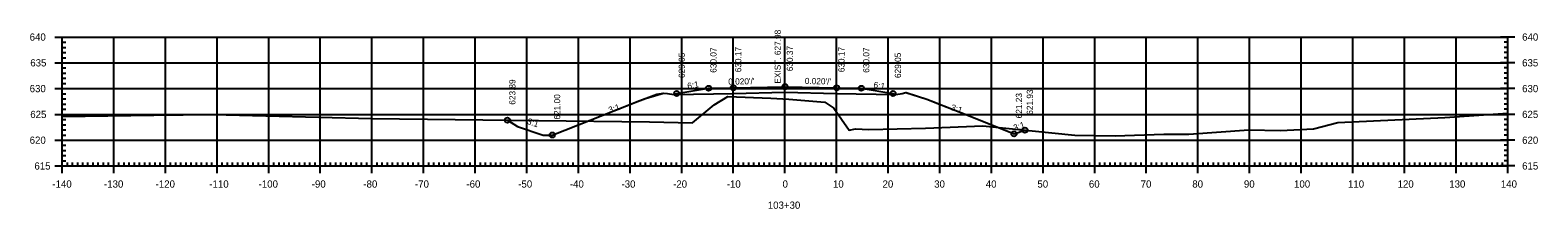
# Model space of a CAD drawing. Extents: x 1381471 to 1382703, y 370300 to 371487.
# Drawn here: x 1381470.8 to 1381762.9, y 370986 to 371020.6 of the extents above; entities that cross this region are included whole.
import ezdxf

# ---------------------------------------------------------------- set-up
doc = ezdxf.new("R2010")
doc.units = 0
for name, color, linetype in [('Level 18', 7, 'Continuous'), ('Level 2', 7, 'Continuous'), ('Level 20', 7, 'Continuous'), ('Level 22', 7, 'Continuous'), ('Level 26', 7, 'Continuous'), ('Level 4', 7, 'Continuous'), ('Level 41', 7, 'Continuous'), ('Level 42', 7, 'Continuous'), ('Level 5', 7, 'Continuous')]:
    doc.layers.add(name, color=color, linetype=linetype)

msp = doc.modelspace()

# ---------------------------------------------------------------- linework, layer by layer
at = {"layer": 'Level 18'}
msp.add_lwpolyline([(1381477.04, 371003.91), (1381494.82, 371004.16), (1381506.23, 371004.28), (1381537.05, 371003.5), (1381590.81, 371002.84), (1381599.15, 371002.68), (1381603.34, 371006.17), (1381605.99, 371007.73), (1381614.34, 371007.44), (1381617.77, 371007.22), (1381624.77, 371006.69), (1381626.52, 371005.47), (1381629.49, 371001.24), (1381630.7, 371001.5), (1381633.29, 371001.37), (1381644.3, 371001.62), (1381655.35, 371002.06), (1381673.21, 371000.23), (1381680.98, 371000.11), (1381690.46, 371000.44), (1381695.27, 371000.45), (1381706.9, 371001.28), (1381713.02, 371001.18), (1381719.4, 371001.52), (1381724.17, 371002.74), (1381744.89, 371003.67), (1381757.04, 371004.53)], dxfattribs=at)
at = {"layer": 'Level 2'}
msp.add_lwpolyline([(1381595.52, 371008.14), (1381607.04, 371008.37), (1381617.04, 371008.57), (1381627.04, 371008.37), (1381638.55, 371008.14)], dxfattribs=at)
at = {"layer": 'Level 20'}
msp.add_lwpolyline([(1381563.29, 371003.17), (1381565.24, 371001.94), (1381570.2, 371000.29), (1381571.96, 371000.29), (1381581.74, 371004.13), (1381588.48, 371006.76), (1381590.05, 371007.39), (1381593.49, 371008.43), (1381594.29, 371008.32), (1381595.52, 371008.14), (1381596.1, 371008.34), (1381602.24, 371009.36), (1381607.04, 371009.46), (1381617.04, 371009.66), (1381627.04, 371009.46), (1381631.83, 371009.36), (1381637.97, 371008.34), (1381638.55, 371008.14), (1381639.75, 371008.37), (1381640.49, 371008.51), (1381644.52, 371007.26), (1381646.17, 371006.59), (1381651.94, 371004.31), (1381661.42, 371000.52), (1381663.53, 371001.22)], dxfattribs=at)
at = {"layer": 'Level 22'}
for p, q in [((1381477.04, 371019.29), (1381757.04, 371019.29)), ((1381477.04, 370994.29), (1381477.04, 371019.29)), ((1381487.04, 370994.29), (1381487.04, 371019.29)), ((1381497.04, 370994.29), (1381497.04, 371019.29)), ((1381507.04, 370994.29), (1381507.04, 371019.29)), ((1381517.04, 370994.29), (1381517.04, 371019.29)), ((1381527.04, 370994.29), (1381527.04, 371019.29)), ((1381537.04, 370994.29), (1381537.04, 371019.29)), ((1381547.04, 370994.29), (1381547.04, 371019.29)), ((1381557.04, 370994.29), (1381557.04, 371019.29)), ((1381567.04, 370994.29), (1381567.04, 371019.29)), ((1381577.04, 370994.29), (1381577.04, 371019.29)), ((1381587.04, 370994.29), (1381587.04, 371019.29)), ((1381597.04, 370994.29), (1381597.04, 371019.29)), ((1381607.04, 370994.29), (1381607.04, 371019.29)), ((1381617.04, 370994.29), (1381617.04, 371019.29)), ((1381627.04, 370994.29), (1381627.04, 371019.29)), ((1381637.04, 370994.29), (1381637.04, 371019.29)), ((1381647.04, 370994.29), (1381647.04, 371019.29)), ((1381657.04, 370994.29), (1381657.04, 371019.29)), ((1381667.04, 370994.29), (1381667.04, 371019.29)), ((1381677.04, 370994.29), (1381677.04, 371019.29)), ((1381687.04, 370994.29), (1381687.04, 371019.29)), ((1381697.04, 370994.29), (1381697.04, 371019.29)), ((1381707.04, 370994.29), (1381707.04, 371019.29)), ((1381717.04, 370994.29), (1381717.04, 371019.29)), ((1381727.04, 370994.29), (1381727.04, 371019.29)), ((1381737.04, 370994.29), (1381737.04, 371019.29)), ((1381747.04, 370994.29), (1381747.04, 371019.29)), ((1381757.04, 370994.29), (1381757.04, 371019.29)), ((1381477.04, 371014.29), (1381757.04, 371014.29)), ((1381477.04, 371009.29), (1381757.04, 371009.29)), ((1381477.04, 371004.29), (1381757.04, 371004.29)), ((1381477.04, 370999.29), (1381757.04, 370999.29)), ((1381477.04, 370994.29), (1381757.04, 370994.29))]:
    msp.add_line(p, q, dxfattribs=at)
at = {"layer": 'Level 26'}
msp.add_lwpolyline([(1381563.29, 371003.17), (1381565.24, 371001.94), (1381570.2, 371000.29), (1381571.96, 371000.29), (1381581.74, 371004.13), (1381588.32, 371006.72), (1381588.43, 371006.76), (1381592.23, 371008.19), (1381593.48, 371008.43), (1381593.49, 371008.43), (1381594.29, 371008.32), (1381595.52, 371008.14), (1381596.1, 371008.34), (1381602.24, 371009.36), (1381607.04, 371009.46), (1381617.04, 371009.66), (1381627.04, 371009.46), (1381631.83, 371009.36), (1381637.97, 371008.34), (1381638.55, 371008.14), (1381639.75, 371008.37), (1381640.49, 371008.51), (1381640.51, 371008.51), (1381644.56, 371007.26), (1381646.23, 371006.59), (1381646.34, 371006.55), (1381651.94, 371004.31), (1381661.42, 371000.52), (1381663.53, 371001.22)], dxfattribs=at)
for centre in [(1381596.1, 371008.34), (1381602.24, 371009.36), (1381607.04, 371009.46), (1381617.04, 371009.66), (1381627.04, 371009.46), (1381631.83, 371009.36), (1381637.97, 371008.34), (1381563.29, 371003.17), (1381571.96, 371000.29), (1381571.96, 371000.29), (1381661.42, 371000.52), (1381661.42, 371000.52), (1381663.53, 371001.22)]:
    msp.add_circle(centre, 0.5, dxfattribs=at)
at = {"layer": 'Level 4'}
for p, q in [((1381475.64, 371019.29), (1381478.44, 371019.29)), ((1381477.04, 370994.29), (1381477.04, 371019.29)), ((1381477.04, 371018.29), (1381477.74, 371018.29)), ((1381477.04, 371017.29), (1381477.74, 371017.29)), ((1381758.44, 371019.29), (1381755.64, 371019.29)), ((1381757.04, 371018.29), (1381756.34, 371018.29)), ((1381757.04, 371017.29), (1381756.34, 371017.29)), ((1381757.04, 370994.29), (1381757.04, 371019.29)), ((1381477.04, 371016.29), (1381477.74, 371016.29)), ((1381477.04, 371015.29), (1381477.74, 371015.29)), ((1381757.04, 371016.29), (1381756.34, 371016.29)), ((1381757.04, 371015.29), (1381756.34, 371015.29)), ((1381475.64, 371014.29), (1381478.44, 371014.29)), ((1381477.04, 371013.29), (1381477.74, 371013.29)), ((1381477.04, 371012.29), (1381477.74, 371012.29)), ((1381758.44, 371014.29), (1381755.64, 371014.29)), ((1381757.04, 371013.29), (1381756.34, 371013.29)), ((1381757.04, 371012.29), (1381756.34, 371012.29)), ((1381475.64, 371009.29), (1381478.44, 371009.29)), ((1381477.04, 371011.29), (1381477.74, 371011.29)), ((1381477.04, 371010.29), (1381477.74, 371010.29)), ((1381758.44, 371009.29), (1381755.64, 371009.29)), ((1381757.04, 371011.29), (1381756.34, 371011.29)), ((1381757.04, 371010.29), (1381756.34, 371010.29)), ((1381477.04, 371008.29), (1381477.74, 371008.29)), ((1381477.04, 371007.29), (1381477.74, 371007.29)), ((1381477.04, 371006.29), (1381477.74, 371006.29)), ((1381757.04, 371008.29), (1381756.34, 371008.29)), ((1381757.04, 371007.29), (1381756.34, 371007.29)), ((1381757.04, 371006.29), (1381756.34, 371006.29)), ((1381475.64, 371004.29), (1381478.44, 371004.29)), ((1381477.04, 371005.29), (1381477.74, 371005.29)), ((1381477.04, 371003.29), (1381477.74, 371003.29)), ((1381758.44, 371004.29), (1381755.64, 371004.29)), ((1381757.04, 371005.29), (1381756.34, 371005.29)), ((1381757.04, 371003.29), (1381756.34, 371003.29)), ((1381477.04, 371002.29), (1381477.74, 371002.29)), ((1381477.04, 371001.29), (1381477.74, 371001.29)), ((1381477.04, 371000.29), (1381477.74, 371000.29)), ((1381757.04, 371002.29), (1381756.34, 371002.29)), ((1381757.04, 371001.29), (1381756.34, 371001.29)), ((1381757.04, 371000.29), (1381756.34, 371000.29)), ((1381475.64, 370999.29), (1381478.44, 370999.29)), ((1381477.04, 370998.29), (1381477.74, 370998.29)), ((1381477.04, 370997.29), (1381477.74, 370997.29)), ((1381758.44, 370999.29), (1381755.64, 370999.29)), ((1381757.04, 370998.29), (1381756.34, 370998.29)), ((1381757.04, 370997.29), (1381756.34, 370997.29)), ((1381475.64, 370994.29), (1381478.44, 370994.29)), ((1381477.04, 370996.29), (1381477.74, 370996.29)), ((1381477.04, 370992.89), (1381477.04, 370995.69)), ((1381477.04, 370995.29), (1381477.74, 370995.29)), ((1381477.04, 370994.29), (1381757.04, 370994.29)), ((1381478.04, 370994.29), (1381478.04, 370994.99)), ((1381479.04, 370994.29), (1381479.04, 370994.99)), ((1381480.04, 370994.29), (1381480.04, 370994.99)), ((1381481.04, 370994.29), (1381481.04, 370994.99)), ((1381482.04, 370994.29), (1381482.04, 370994.99)), ((1381483.04, 370994.29), (1381483.04, 370994.99)), ((1381484.04, 370994.29), (1381484.04, 370994.99)), ((1381485.04, 370994.29), (1381485.04, 370994.99)), ((1381486.04, 370994.29), (1381486.04, 370994.99)), ((1381487.04, 370992.89), (1381487.04, 370995.69)), ((1381488.04, 370994.29), (1381488.04, 370994.99)), ((1381489.04, 370994.29), (1381489.04, 370994.99)), ((1381490.04, 370994.29), (1381490.04, 370994.99)), ((1381491.04, 370994.29), (1381491.04, 370994.99)), ((1381492.04, 370994.29), (1381492.04, 370994.99)), ((1381493.04, 370994.29), (1381493.04, 370994.99)), ((1381494.04, 370994.29), (1381494.04, 370994.99)), ((1381495.04, 370994.29), (1381495.04, 370994.99)), ((1381496.04, 370994.29), (1381496.04, 370994.99)), ((1381497.04, 370992.89), (1381497.04, 370995.69)), ((1381498.04, 370994.29), (1381498.04, 370994.99)), ((1381499.04, 370994.29), (1381499.04, 370994.99)), ((1381500.04, 370994.29), (1381500.04, 370994.99)), ((1381501.04, 370994.29), (1381501.04, 370994.99)), ((1381502.04, 370994.29), (1381502.04, 370994.99)), ((1381503.04, 370994.29), (1381503.04, 370994.99)), ((1381504.04, 370994.29), (1381504.04, 370994.99)), ((1381505.04, 370994.29), (1381505.04, 370994.99)), ((1381506.04, 370994.29), (1381506.04, 370994.99)), ((1381507.04, 370992.89), (1381507.04, 370995.69)), ((1381508.04, 370994.29), (1381508.04, 370994.99)), ((1381509.04, 370994.29), (1381509.04, 370994.99)), ((1381510.04, 370994.29), (1381510.04, 370994.99)), ((1381511.04, 370994.29), (1381511.04, 370994.99)), ((1381512.04, 370994.29), (1381512.04, 370994.99)), ((1381513.04, 370994.29), (1381513.04, 370994.99)), ((1381514.04, 370994.29), (1381514.04, 370994.99)), ((1381515.04, 370994.29), (1381515.04, 370994.99)), ((1381516.04, 370994.29), (1381516.04, 370994.99)), ((1381517.04, 370992.89), (1381517.04, 370995.69)), ((1381518.04, 370994.29), (1381518.04, 370994.99)), ((1381519.04, 370994.29), (1381519.04, 370994.99)), ((1381520.04, 370994.29), (1381520.04, 370994.99)), ((1381521.04, 370994.29), (1381521.04, 370994.99)), ((1381522.04, 370994.29), (1381522.04, 370994.99)), ((1381523.04, 370994.29), (1381523.04, 370994.99)), ((1381524.04, 370994.29), (1381524.04, 370994.99)), ((1381525.04, 370994.29), (1381525.04, 370994.99)), ((1381526.04, 370994.29), (1381526.04, 370994.99)), ((1381527.04, 370992.89), (1381527.04, 370995.69)), ((1381528.04, 370994.29), (1381528.04, 370994.99)), ((1381529.04, 370994.29), (1381529.04, 370994.99)), ((1381530.04, 370994.29), (1381530.04, 370994.99)), ((1381531.04, 370994.29), (1381531.04, 370994.99)), ((1381532.04, 370994.29), (1381532.04, 370994.99)), ((1381533.04, 370994.29), (1381533.04, 370994.99)), ((1381534.04, 370994.29), (1381534.04, 370994.99)), ((1381535.04, 370994.29), (1381535.04, 370994.99)), ((1381536.04, 370994.29), (1381536.04, 370994.99)), ((1381537.04, 370992.89), (1381537.04, 370995.69)), ((1381538.04, 370994.29), (1381538.04, 370994.99)), ((1381539.04, 370994.29), (1381539.04, 370994.99)), ((1381540.04, 370994.29), (1381540.04, 370994.99)), ((1381541.04, 370994.29), (1381541.04, 370994.99)), ((1381542.04, 370994.29), (1381542.04, 370994.99)), ((1381543.04, 370994.29), (1381543.04, 370994.99)), ((1381544.04, 370994.29), (1381544.04, 370994.99)), ((1381545.04, 370994.29), (1381545.04, 370994.99)), ((1381546.04, 370994.29), (1381546.04, 370994.99)), ((1381547.04, 370992.89), (1381547.04, 370995.69)), ((1381548.04, 370994.29), (1381548.04, 370994.99)), ((1381549.04, 370994.29), (1381549.04, 370994.99)), ((1381550.04, 370994.29), (1381550.04, 370994.99)), ((1381551.04, 370994.29), (1381551.04, 370994.99)), ((1381552.04, 370994.29), (1381552.04, 370994.99)), ((1381553.04, 370994.29), (1381553.04, 370994.99)), ((1381554.04, 370994.29), (1381554.04, 370994.99)), ((1381555.04, 370994.29), (1381555.04, 370994.99)), ((1381556.04, 370994.29), (1381556.04, 370994.99)), ((1381557.04, 370992.89), (1381557.04, 370995.69)), ((1381558.04, 370994.29), (1381558.04, 370994.99)), ((1381559.04, 370994.29), (1381559.04, 370994.99)), ((1381560.04, 370994.29), (1381560.04, 370994.99)), ((1381561.04, 370994.29), (1381561.04, 370994.99)), ((1381562.04, 370994.29), (1381562.04, 370994.99)), ((1381563.04, 370994.29), (1381563.04, 370994.99)), ((1381564.04, 370994.29), (1381564.04, 370994.99)), ((1381565.04, 370994.29), (1381565.04, 370994.99)), ((1381566.04, 370994.29), (1381566.04, 370994.99)), ((1381567.04, 370992.89), (1381567.04, 370995.69)), ((1381568.04, 370994.29), (1381568.04, 370994.99)), ((1381569.04, 370994.29), (1381569.04, 370994.99)), ((1381570.04, 370994.29), (1381570.04, 370994.99)), ((1381571.04, 370994.29), (1381571.04, 370994.99)), ((1381572.04, 370994.29), (1381572.04, 370994.99)), ((1381573.04, 370994.29), (1381573.04, 370994.99)), ((1381574.04, 370994.29), (1381574.04, 370994.99)), ((1381575.04, 370994.29), (1381575.04, 370994.99)), ((1381576.04, 370994.29), (1381576.04, 370994.99)), ((1381577.04, 370992.89), (1381577.04, 370995.69)), ((1381578.04, 370994.29), (1381578.04, 370994.99)), ((1381579.04, 370994.29), (1381579.04, 370994.99)), ((1381580.04, 370994.29), (1381580.04, 370994.99)), ((1381581.04, 370994.29), (1381581.04, 370994.99)), ((1381582.04, 370994.29), (1381582.04, 370994.99)), ((1381583.04, 370994.29), (1381583.04, 370994.99)), ((1381584.04, 370994.29), (1381584.04, 370994.99)), ((1381585.04, 370994.29), (1381585.04, 370994.99)), ((1381586.04, 370994.29), (1381586.04, 370994.99)), ((1381587.04, 370992.89), (1381587.04, 370995.69)), ((1381588.04, 370994.29), (1381588.04, 370994.99)), ((1381589.04, 370994.29), (1381589.04, 370994.99)), ((1381590.04, 370994.29), (1381590.04, 370994.99)), ((1381591.04, 370994.29), (1381591.04, 370994.99)), ((1381592.04, 370994.29), (1381592.04, 370994.99)), ((1381593.04, 370994.29), (1381593.04, 370994.99)), ((1381594.04, 370994.29), (1381594.04, 370994.99)), ((1381595.04, 370994.29), (1381595.04, 370994.99)), ((1381596.04, 370994.29), (1381596.04, 370994.99)), ((1381597.04, 370992.89), (1381597.04, 370995.69)), ((1381598.04, 370994.29), (1381598.04, 370994.99)), ((1381599.04, 370994.29), (1381599.04, 370994.99)), ((1381600.04, 370994.29), (1381600.04, 370994.99)), ((1381601.04, 370994.29), (1381601.04, 370994.99)), ((1381602.04, 370994.29), (1381602.04, 370994.99)), ((1381603.04, 370994.29), (1381603.04, 370994.99)), ((1381604.04, 370994.29), (1381604.04, 370994.99)), ((1381605.04, 370994.29), (1381605.04, 370994.99)), ((1381606.04, 370994.29), (1381606.04, 370994.99)), ((1381607.04, 370992.89), (1381607.04, 370995.69)), ((1381608.04, 370994.29), (1381608.04, 370994.99)), ((1381609.04, 370994.29), (1381609.04, 370994.99)), ((1381610.04, 370994.29), (1381610.04, 370994.99)), ((1381611.04, 370994.29), (1381611.04, 370994.99)), ((1381612.04, 370994.29), (1381612.04, 370994.99)), ((1381613.04, 370994.29), (1381613.04, 370994.99)), ((1381614.04, 370994.29), (1381614.04, 370994.99)), ((1381615.04, 370994.29), (1381615.04, 370994.99)), ((1381616.04, 370994.29), (1381616.04, 370994.99)), ((1381617.04, 370992.89), (1381617.04, 370995.69)), ((1381618.04, 370994.29), (1381618.04, 370994.99)), ((1381619.04, 370994.29), (1381619.04, 370994.99)), ((1381620.04, 370994.29), (1381620.04, 370994.99)), ((1381621.04, 370994.29), (1381621.04, 370994.99)), ((1381622.04, 370994.29), (1381622.04, 370994.99)), ((1381623.04, 370994.29), (1381623.04, 370994.99)), ((1381624.04, 370994.29), (1381624.04, 370994.99)), ((1381625.04, 370994.29), (1381625.04, 370994.99)), ((1381626.04, 370994.29), (1381626.04, 370994.99)), ((1381627.04, 370992.89), (1381627.04, 370995.69)), ((1381628.04, 370994.29), (1381628.04, 370994.99)), ((1381629.04, 370994.29), (1381629.04, 370994.99)), ((1381630.04, 370994.29), (1381630.04, 370994.99)), ((1381631.04, 370994.29), (1381631.04, 370994.99)), ((1381632.04, 370994.29), (1381632.04, 370994.99)), ((1381633.04, 370994.29), (1381633.04, 370994.99)), ((1381634.04, 370994.29), (1381634.04, 370994.99)), ((1381635.04, 370994.29), (1381635.04, 370994.99)), ((1381636.04, 370994.29), (1381636.04, 370994.99)), ((1381637.04, 370992.89), (1381637.04, 370995.69)), ((1381638.04, 370994.29), (1381638.04, 370994.99)), ((1381639.04, 370994.29), (1381639.04, 370994.99)), ((1381640.04, 370994.29), (1381640.04, 370994.99)), ((1381641.04, 370994.29), (1381641.04, 370994.99)), ((1381642.04, 370994.29), (1381642.04, 370994.99)), ((1381643.04, 370994.29), (1381643.04, 370994.99)), ((1381644.04, 370994.29), (1381644.04, 370994.99)), ((1381645.04, 370994.29), (1381645.04, 370994.99)), ((1381646.04, 370994.29), (1381646.04, 370994.99)), ((1381647.04, 370992.89), (1381647.04, 370995.69)), ((1381648.04, 370994.29), (1381648.04, 370994.99)), ((1381649.04, 370994.29), (1381649.04, 370994.99)), ((1381650.04, 370994.29), (1381650.04, 370994.99)), ((1381651.04, 370994.29), (1381651.04, 370994.99)), ((1381652.04, 370994.29), (1381652.04, 370994.99)), ((1381653.04, 370994.29), (1381653.04, 370994.99)), ((1381654.04, 370994.29), (1381654.04, 370994.99)), ((1381655.04, 370994.29), (1381655.04, 370994.99)), ((1381656.04, 370994.29), (1381656.04, 370994.99)), ((1381657.04, 370992.89), (1381657.04, 370995.69)), ((1381658.04, 370994.29), (1381658.04, 370994.99)), ((1381659.04, 370994.29), (1381659.04, 370994.99)), ((1381660.04, 370994.29), (1381660.04, 370994.99)), ((1381661.04, 370994.29), (1381661.04, 370994.99)), ((1381662.04, 370994.29), (1381662.04, 370994.99)), ((1381663.04, 370994.29), (1381663.04, 370994.99)), ((1381664.04, 370994.29), (1381664.04, 370994.99)), ((1381665.04, 370994.29), (1381665.04, 370994.99)), ((1381666.04, 370994.29), (1381666.04, 370994.99)), ((1381667.04, 370992.89), (1381667.04, 370995.69)), ((1381668.04, 370994.29), (1381668.04, 370994.99)), ((1381669.04, 370994.29), (1381669.04, 370994.99)), ((1381670.04, 370994.29), (1381670.04, 370994.99)), ((1381671.04, 370994.29), (1381671.04, 370994.99)), ((1381672.04, 370994.29), (1381672.04, 370994.99)), ((1381673.04, 370994.29), (1381673.04, 370994.99)), ((1381674.04, 370994.29), (1381674.04, 370994.99)), ((1381675.04, 370994.29), (1381675.04, 370994.99)), ((1381676.04, 370994.29), (1381676.04, 370994.99)), ((1381677.04, 370992.89), (1381677.04, 370995.69)), ((1381678.04, 370994.29), (1381678.04, 370994.99)), ((1381679.04, 370994.29), (1381679.04, 370994.99)), ((1381680.04, 370994.29), (1381680.04, 370994.99)), ((1381681.04, 370994.29), (1381681.04, 370994.99)), ((1381682.04, 370994.29), (1381682.04, 370994.99)), ((1381683.04, 370994.29), (1381683.04, 370994.99)), ((1381684.04, 370994.29), (1381684.04, 370994.99)), ((1381685.04, 370994.29), (1381685.04, 370994.99)), ((1381686.04, 370994.29), (1381686.04, 370994.99)), ((1381687.04, 370992.89), (1381687.04, 370995.69)), ((1381688.04, 370994.29), (1381688.04, 370994.99)), ((1381689.04, 370994.29), (1381689.04, 370994.99)), ((1381690.04, 370994.29), (1381690.04, 370994.99)), ((1381691.04, 370994.29), (1381691.04, 370994.99)), ((1381692.04, 370994.29), (1381692.04, 370994.99)), ((1381693.04, 370994.29), (1381693.04, 370994.99)), ((1381694.04, 370994.29), (1381694.04, 370994.99)), ((1381695.04, 370994.29), (1381695.04, 370994.99)), ((1381696.04, 370994.29), (1381696.04, 370994.99)), ((1381697.04, 370992.89), (1381697.04, 370995.69)), ((1381698.04, 370994.29), (1381698.04, 370994.99)), ((1381699.04, 370994.29), (1381699.04, 370994.99)), ((1381700.04, 370994.29), (1381700.04, 370994.99)), ((1381701.04, 370994.29), (1381701.04, 370994.99)), ((1381702.04, 370994.29), (1381702.04, 370994.99)), ((1381703.04, 370994.29), (1381703.04, 370994.99)), ((1381704.04, 370994.29), (1381704.04, 370994.99)), ((1381705.04, 370994.29), (1381705.04, 370994.99)), ((1381706.04, 370994.29), (1381706.04, 370994.99)), ((1381707.04, 370992.89), (1381707.04, 370995.69)), ((1381708.04, 370994.29), (1381708.04, 370994.99)), ((1381709.04, 370994.29), (1381709.04, 370994.99)), ((1381710.04, 370994.29), (1381710.04, 370994.99)), ((1381711.04, 370994.29), (1381711.04, 370994.99)), ((1381712.04, 370994.29), (1381712.04, 370994.99)), ((1381713.04, 370994.29), (1381713.04, 370994.99)), ((1381714.04, 370994.29), (1381714.04, 370994.99)), ((1381715.04, 370994.29), (1381715.04, 370994.99)), ((1381716.04, 370994.29), (1381716.04, 370994.99)), ((1381717.04, 370992.89), (1381717.04, 370995.69)), ((1381718.04, 370994.29), (1381718.04, 370994.99)), ((1381719.04, 370994.29), (1381719.04, 370994.99)), ((1381720.04, 370994.29), (1381720.04, 370994.99)), ((1381721.04, 370994.29), (1381721.04, 370994.99)), ((1381722.04, 370994.29), (1381722.04, 370994.99)), ((1381723.04, 370994.29), (1381723.04, 370994.99)), ((1381724.04, 370994.29), (1381724.04, 370994.99)), ((1381725.04, 370994.29), (1381725.04, 370994.99)), ((1381726.04, 370994.29), (1381726.04, 370994.99)), ((1381727.04, 370992.89), (1381727.04, 370995.69)), ((1381728.04, 370994.29), (1381728.04, 370994.99)), ((1381729.04, 370994.29), (1381729.04, 370994.99)), ((1381730.04, 370994.29), (1381730.04, 370994.99)), ((1381731.04, 370994.29), (1381731.04, 370994.99)), ((1381732.04, 370994.29), (1381732.04, 370994.99)), ((1381733.04, 370994.29), (1381733.04, 370994.99)), ((1381734.04, 370994.29), (1381734.04, 370994.99)), ((1381735.04, 370994.29), (1381735.04, 370994.99)), ((1381736.04, 370994.29), (1381736.04, 370994.99)), ((1381737.04, 370992.89), (1381737.04, 370995.69)), ((1381738.04, 370994.29), (1381738.04, 370994.99)), ((1381739.04, 370994.29), (1381739.04, 370994.99)), ((1381740.04, 370994.29), (1381740.04, 370994.99)), ((1381741.04, 370994.29), (1381741.04, 370994.99)), ((1381742.04, 370994.29), (1381742.04, 370994.99)), ((1381743.04, 370994.29), (1381743.04, 370994.99)), ((1381744.04, 370994.29), (1381744.04, 370994.99)), ((1381745.04, 370994.29), (1381745.04, 370994.99)), ((1381746.04, 370994.29), (1381746.04, 370994.99)), ((1381747.04, 370992.89), (1381747.04, 370995.69)), ((1381748.04, 370994.29), (1381748.04, 370994.99)), ((1381749.04, 370994.29), (1381749.04, 370994.99)), ((1381750.04, 370994.29), (1381750.04, 370994.99)), ((1381751.04, 370994.29), (1381751.04, 370994.99)), ((1381752.04, 370994.29), (1381752.04, 370994.99)), ((1381753.04, 370994.29), (1381753.04, 370994.99)), ((1381754.04, 370994.29), (1381754.04, 370994.99)), ((1381755.04, 370994.29), (1381755.04, 370994.99)), ((1381758.44, 370994.29), (1381755.64, 370994.29)), ((1381756.04, 370994.29), (1381756.04, 370994.99)), ((1381757.04, 370996.29), (1381756.34, 370996.29)), ((1381757.04, 370995.29), (1381756.34, 370995.29)), ((1381757.04, 370992.89), (1381757.04, 370995.69))]:
    msp.add_line(p, q, dxfattribs=at)

# ---------------------------------------------------------------- texts
at = {"layer": 'Level 41'}
for s, p in [('EXIST. 627.98', (1381616.24, 371010.26)), ('630.17', (1381608.59, 371012.46)), ('630.37', (1381618.59, 371012.66)), ('630.17', (1381628.59, 371012.46)), ('629.05', (1381597.65, 371011.34)), ('630.07', (1381603.79, 371012.36)), ('630.07', (1381633.38, 371012.36)), ('629.05', (1381639.52, 371011.34)), ('623.89', (1381564.84, 371006.17)), ('621.93', (1381665.08, 371004.22)), ('621.00', (1381573.51, 371003.29)), ('621.23', (1381662.97, 371003.52))]:
    msp.add_text(s, height=1.2, rotation=90, dxfattribs=at).set_placement(p)
at = {"layer": 'Level 42'}
for s, rotation, p in [("0.020'/'", 1.1458, (1381606.07, 371010.04)), ("0.020'/'", 358.8542, (1381620.88, 371010.18)), ('6:1', 9.4623, (1381598.24, 371009.2)), ('6:1', 350.5375, (1381634.13, 371009.48)), ('3:1', 18.4349, (1381583.08, 371004.52)), ('3:1', 341.5651, (1381649.06, 371005.16)), ('3:1', 341.5651, (1381566.99, 371002.47)), ('3:1', 18.4349, (1381661.53, 371001.08))]:
    msp.add_text(s, height=1.2, rotation=rotation, dxfattribs=at).set_placement(p)
at = {"layer": 'Level 5'}
for s, p in [('640', (1381470.74, 371018.59)), ('640', (1381759.84, 371018.59)), ('635', (1381470.86, 371013.59)), ('635', (1381759.84, 371013.59)), ('630', (1381470.74, 371008.59)), ('630', (1381759.84, 371008.59)), ('625', (1381470.86, 371003.59)), ('625', (1381759.84, 371003.59)), ('620', (1381470.74, 370998.59)), ('620', (1381759.84, 370998.59)), ('615', (1381471.66, 370993.59)), ('615', (1381759.84, 370993.59)), ('-140', (1381475.14, 370990.09)), ('-130', (1381485.14, 370990.09)), ('-120', (1381495.14, 370990.09)), ('-110', (1381505.54, 370990.09)), ('-100', (1381515.09, 370990.09)), ('-90', (1381525.38, 370990.09)), ('-80', (1381535.38, 370990.09)), ('-70', (1381545.38, 370990.09)), ('-60', (1381555.34, 370990.09)), ('-50', (1381565.38, 370990.09)), ('-40', (1381575.38, 370990.09)), ('-30', (1381585.38, 370990.09)), ('-20', (1381595.38, 370990.09)), ('-10', (1381605.77, 370990.09)), ('0', (1381616.58, 370990.09)), ('10', (1381626.35, 370990.09)), ('20', (1381635.95, 370990.09)), ('30', (1381645.95, 370990.09)), ('40', (1381655.95, 370990.09)), ('50', (1381665.95, 370990.09)), ('60', (1381675.92, 370990.09)), ('70', (1381685.95, 370990.09)), ('80', (1381695.95, 370990.09)), ('90', (1381705.95, 370990.09)), ('100', (1381715.66, 370990.09)), ('110', (1381726.11, 370990.09)), ('120', (1381735.72, 370990.09)), ('130', (1381745.72, 370990.09)), ('140', (1381755.72, 370990.09)), ('103+30', (1381613.72, 370985.99))]:
    msp.add_text(s, height=1.4, dxfattribs=at).set_placement(p)

doc.saveas('drawing.dxf')
